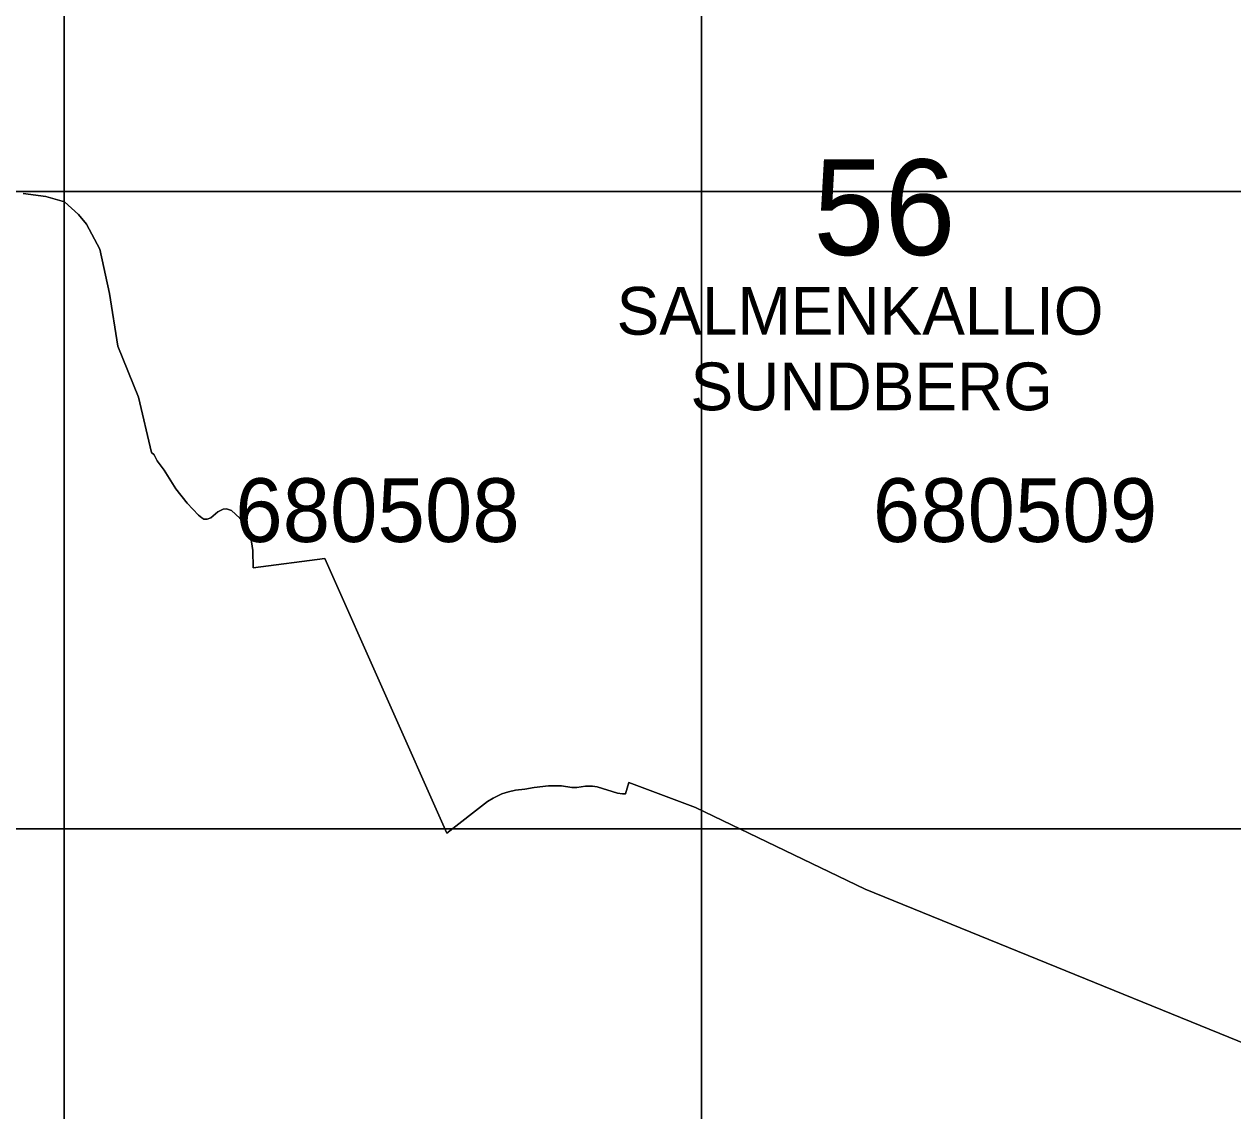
# Model space of a CAD drawing. Extents: x 25485000 to 25520000, y 6656775 to 6690000.
# Drawn here: x 25507937 to 25509833, y 6679557 to 6681263 of the extents above; entities that cross this region are included whole.
import ezdxf

# ---------------------------------------------------------------- set-up
doc = ezdxf.new("R2010")
doc.units = 0
doc.layers.add('Level 63', color=7, linetype='Continuous')

msp = doc.modelspace()

# ---------------------------------------------------------------- linework, layer by layer
at = {"layer": 'Level 63'}
for points in [[(25507000, 6681000), (25508000, 6681000), (25508000, 6682000), (25507000, 6682000)], [(25508000, 6681000), (25509000, 6681000), (25509000, 6682000), (25508000, 6682000)], [(25509000, 6681000), (25510000, 6681000), (25510000, 6682000), (25509000, 6682000)], [(25507000, 6680000), (25508000, 6680000), (25508000, 6681000), (25507000, 6681000)], [(25508000, 6680000), (25509000, 6680000), (25509000, 6681000), (25508000, 6681000)], [(25509000, 6680000), (25510000, 6680000), (25510000, 6681000), (25509000, 6681000)], [(25507000, 6679000), (25508000, 6679000), (25508000, 6680000), (25507000, 6680000)], [(25508000, 6679000), (25509000, 6679000), (25509000, 6680000), (25508000, 6680000)], [(25509000, 6679000), (25510000, 6679000), (25510000, 6680000), (25509000, 6680000)]]:
    msp.add_lwpolyline(points, close=True, dxfattribs=at)
for points in [[(25507935.9, 6680997), (25507971.5, 6680992.5), (25508000.9, 6680984.1), (25508022.6, 6680964.1), (25508035.4, 6680949.1), (25508055.9, 6680909.6), (25508071.5, 6680840.2), (25508084.2, 6680757.4), (25508116.6, 6680677.5), (25508137.2, 6680590.3), (25508141.2, 6680586.8), (25508146.1, 6680577.4), (25508156.9, 6680562.6), (25508175.1, 6680533.5), (25508193.3, 6680510.8), (25508211, 6680492.1), (25508216, 6680488.1), (25508219.4, 6680485.7), (25508224.3, 6680485.7), (25508230.2, 6680487.9), (25508241.3, 6680497.1), (25508249.3, 6680501.6), (25508255, 6680502.2), (25508262.8, 6680499.2), (25508275.7, 6680487.4), (25508284.7, 6680477), (25508292.3, 6680460), (25508296.2, 6680436.5), (25508296.7, 6680409.3), (25508409, 6680424.3), (25508600.3, 6679993.2), (25508664.1, 6680042.7), (25508673, 6680048), (25508686.4, 6680054.6), (25508696.9, 6680058), (25508708, 6680060.3), (25508722.8, 6680061.8), (25508737.4, 6680064.8), (25508759.9, 6680067.3), (25508780, 6680067.3), (25508796.2, 6680064.6), (25508804.4, 6680064.6), (25508818.1, 6680066.6), (25508828.6, 6680066.8), (25508836.4, 6680065.8), (25508867.9, 6680055.9), (25508875.8, 6680054.9), (25508880.7, 6680054.9), (25508885.8, 6680072.6), (25508990.3, 6680033.2), (25509256.4, 6679905), (25510096.8, 6679562.8)], [(25510096.8, 6679562.8), (25509256.4, 6679905), (25508990.3, 6680033.2), (25508885.8, 6680072.6), (25508880.7, 6680054.9), (25508875.8, 6680054.9), (25508867.9, 6680055.9), (25508836.4, 6680065.8), (25508828.6, 6680066.8), (25508818.1, 6680066.6), (25508804.4, 6680064.6), (25508796.2, 6680064.6), (25508780, 6680067.3), (25508759.9, 6680067.3), (25508737.4, 6680064.8), (25508722.8, 6680061.8), (25508708, 6680060.3), (25508696.9, 6680058), (25508686.4, 6680054.6), (25508673, 6680048), (25508664.1, 6680042.7), (25508600.3, 6679993.2), (25508409, 6680424.3), (25508296.7, 6680409.3), (25508296.2, 6680436.5), (25508292.3, 6680460), (25508284.7, 6680477), (25508275.7, 6680487.4), (25508262.8, 6680499.2), (25508255, 6680502.2), (25508249.3, 6680501.6), (25508241.3, 6680497.1), (25508230.2, 6680487.9), (25508224.3, 6680485.7), (25508219.4, 6680485.7), (25508216, 6680488.1), (25508211, 6680492.1), (25508193.3, 6680510.8), (25508175.1, 6680533.5), (25508156.9, 6680562.6), (25508146.1, 6680577.4), (25508141.2, 6680586.8), (25508137.2, 6680590.3), (25508116.6, 6680677.5), (25508084.2, 6680757.4), (25508071.5, 6680840.2), (25508055.9, 6680909.6), (25508035.4, 6680949.1), (25508022.6, 6680964.1), (25508000.9, 6680984.1), (25507971.5, 6680992.5), (25507935.9, 6680997)]]:
    msp.add_lwpolyline(points, dxfattribs=at)

# ---------------------------------------------------------------- texts
for s, height, p in [('56', 150, (25509175.2, 6680900.5)), ('SALMENKALLIO', 75, (25508866.7, 6680775.4)), ('SUNDBERG', 75, (25508982.6, 6680656.7)), ('680508', 100, (25508268.5, 6680450)), ('680509', 100, (25509268.5, 6680450))]:
    msp.add_text(s, height=height, dxfattribs=at).set_placement(p)

doc.saveas('drawing.dxf')
